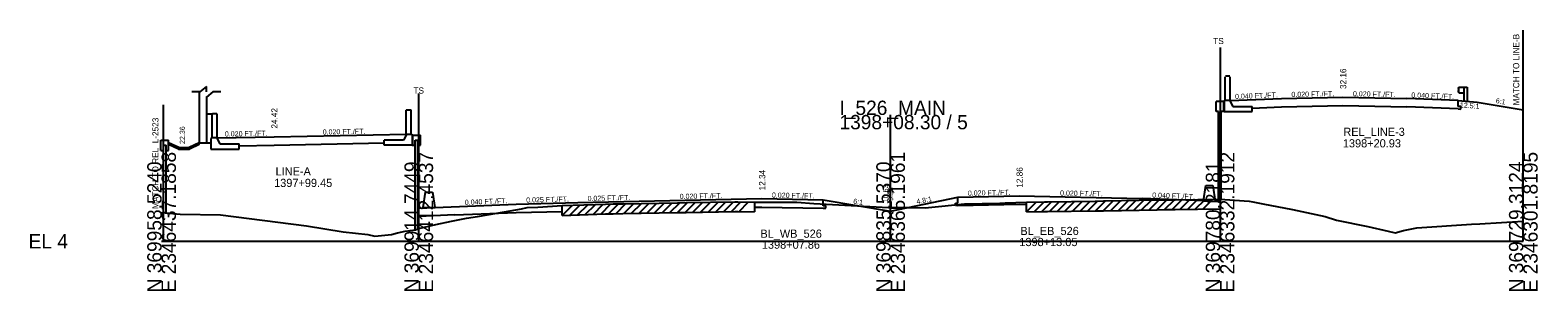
# Model space of a CAD drawing. Extents: x -170 to 2527928, y -10 to 1619750.
# Drawn here: x 1974.3 to 2269.1, y 8490.3 to 8541.3 of the extents above; entities that cross this region are included whole.
import ezdxf

# ---------------------------------------------------------------- set-up
doc = ezdxf.new("R2010")
doc.units = 0
for name, color, linetype in [('Default', 7, 'Continuous'), ('RD_GPK_XS_Cell', 7, 'Continuous'), ('RD_PD_NOISE-WALL-GM', 7, 'Continuous'), ('RD_PD_WallFill', 7, 'Continuous'), ('RD_XS_Base', 7, 'Continuous'), ('RD_XS_EarthShd', 7, 'Continuous'), ('RD_XS_ExGround', 7, 'Continuous'), ('RD_XS_ExPaveRet', 7, 'Continuous'), ('RD_XS_GR', 7, 'Continuous'), ('RD_XS_MatchLine', 7, 'Continuous'), ('RD_XS_Pave', 7, 'Continuous'), ('RD_XS_PaveShd', 7, 'Continuous'), ('RD_XS_TieSlope', 7, 'Continuous'), ('RD_XS_TX_Elev_EX', 7, 'Continuous'), ('RD_XS_TX_Elev_PR', 7, 'Continuous'), ('RD_XS_TX_Slope', 7, 'Continuous'), ('RD_XS_TX_Station', 7, 'Continuous')]:
    doc.layers.add(name, color=color, linetype=linetype)

msp = doc.modelspace()

# ---------------------------------------------------------------- linework, layer by layer
at = {"layer": 'Default'}
for p, q in [((2008.75, 8530.26), (2007.5, 8529.23)), ((2008.75, 8529.23), (2008.75, 8530.26)), ((2007.5, 8529.23), (2005.92, 8529.23)), ((2010, 8529.23), (2008.75, 8528.21)), ((2011.6, 8529.23), (2010, 8529.23))]:
    msp.add_line(p, q, dxfattribs=at)
at = {"layer": 'RD_GPK_XS_Cell'}
for p, q in [((2142.52, 8500), (2142.52, 8524.7)), ((2000, 8500), (2050.28, 8500)), ((2050.28, 8500), (2142.52, 8500)), ((2142.52, 8500), (2206.93, 8500)), ((2206.93, 8500), (2266.21, 8500))]:
    msp.add_line(p, q, dxfattribs=at)
at = {"layer": 'RD_PD_NOISE-WALL-GM'}
for p, q in [((2007.37, 8529.23), (2007.37, 8519.28)), ((2008.87, 8519.28), (2008.87, 8528.31)), ((2051.12, 8506.62), (2051.6, 8509.62)), ((2051.6, 8509.62), (2052.94, 8509.62)), ((2052.94, 8509.62), (2053.43, 8506.62)), ((2203.68, 8507.9), (2204.16, 8510.9)), ((2204.16, 8510.9), (2205.5, 8510.9)), ((2205.5, 8510.9), (2206, 8507.81)), ((2051.12, 8506.62), (2053.43, 8506.62))]:
    msp.add_line(p, q, dxfattribs=at)
at = {"layer": 'RD_PD_WallFill'}
for p, q in [((2207.93, 8527.52), (2207.93, 8532.19)), ((2208.85, 8532.27), (2208.02, 8532.27)), ((2208.93, 8527.52), (2208.93, 8532.19)), ((2206.15, 8525.35), (2206.15, 8527.35)), ((2207.65, 8527.35), (2206.15, 8527.35)), ((2207.65, 8525.35), (2207.65, 8527.35)), ((2207.72, 8527.35), (2207.65, 8527.35)), ((2207.8, 8527.52), (2207.72, 8527.43)), ((2207.72, 8527.43), (2207.72, 8525.35)), ((2208.93, 8527.52), (2207.8, 8527.52)), ((2208.93, 8527.52), (2208.93, 8527.35)), ((2208.93, 8527.35), (2209.43, 8526.35)), ((2009.96, 8524.95), (2009.87, 8524.87)), ((2009.87, 8520.2), (2009.87, 8524.87)), ((2010.79, 8524.95), (2009.96, 8524.95)), ((2010.79, 8524.95), (2010.87, 8524.87)), ((2010.87, 8520.2), (2010.87, 8524.87)), ((2047.89, 8525.69), (2047.8, 8525.61)), ((2047.8, 8520.94), (2047.8, 8525.61)), ((2047.89, 8525.69), (2048.72, 8525.69)), ((2048.72, 8525.69), (2048.8, 8525.61)), ((2048.8, 8520.94), (2048.8, 8525.61)), ((2206.65, 8525.35), (2206.15, 8525.35)), ((2206.65, 8507.78), (2206.65, 8525.35)), ((2207.15, 8508.22), (2207.15, 8525.35)), ((2207.65, 8525.35), (2207.15, 8525.35)), ((2207.72, 8525.35), (2207.65, 8525.35)), ((2207.72, 8525.35), (2213.22, 8525.35)), ((2209.43, 8526.35), (2213.22, 8526.35)), ((2213.22, 8525.35), (2213.22, 8526.35)), ((1999.87, 8519.78), (2001.37, 8519.78)), ((1999.87, 8517.78), (1999.87, 8519.78)), ((2000.37, 8505.59), (2000.37, 8518.78)), ((2000.37, 8518.78), (2000.87, 8518.78)), ((2000.87, 8505.54), (2000.87, 8518.78)), ((2001.37, 8517.78), (2001.37, 8519.78)), ((2003.37, 8518.36), (2001.37, 8519.28)), ((2003.3, 8518.03), (2001.37, 8518.91)), ((2003.37, 8518.36), (2005.37, 8518.36)), ((2007.37, 8519.28), (2005.37, 8518.36)), ((2007.37, 8518.91), (2005.45, 8518.03)), ((2007.37, 8518.91), (2007.37, 8519.28)), ((2009.75, 8520.2), (2009.66, 8520.12)), ((2009.66, 8520.12), (2009.66, 8518.03)), ((2010.87, 8520.2), (2009.75, 8520.2)), ((2010.87, 8520.2), (2010.87, 8520.03)), ((2010.87, 8520.03), (2011.37, 8519.03)), ((2011.37, 8519.03), (2015.16, 8519.03)), ((2015.16, 8518.03), (2015.16, 8519.03)), ((2047.31, 8519.77), (2043.52, 8519.77)), ((2043.52, 8518.77), (2043.52, 8519.77)), ((2049.02, 8518.77), (2043.52, 8518.77)), ((2047.8, 8520.77), (2047.31, 8519.77)), ((2047.8, 8520.94), (2048.93, 8520.94)), ((2047.8, 8520.94), (2047.8, 8520.77)), ((2048.93, 8520.94), (2049.02, 8520.86)), ((2049.02, 8520.86), (2049.02, 8518.77)), ((2049.02, 8520.77), (2049.09, 8520.77)), ((2049.02, 8518.77), (2049.09, 8518.77)), ((2049.09, 8518.77), (2049.09, 8520.77)), ((2049.09, 8520.77), (2050.59, 8520.77)), ((2049.09, 8518.77), (2049.59, 8518.77)), ((2049.59, 8519.77), (2050.09, 8519.77)), ((2049.59, 8502.25), (2049.59, 8519.77)), ((2050.09, 8502.44), (2050.09, 8519.77)), ((2050.09, 8518.77), (2050.59, 8518.77)), ((2050.59, 8518.77), (2050.59, 8520.77)), ((1999.87, 8517.78), (2000.37, 8517.78)), ((2000.87, 8517.78), (2001.37, 8517.78)), ((2003.3, 8518.03), (2005.45, 8518.03)), ((2009.66, 8518.03), (2015.16, 8518.03))]:
    msp.add_line(p, q, dxfattribs=at)
at = {"layer": 'RD_XS_Base'}
for p, q in [((2253.47, 8526.37), (2253.47, 8527.51)), ((2213.22, 8526.05), (2218.93, 8526.28)), ((2218.93, 8526.28), (2230.93, 8526.52)), ((2230.93, 8526.52), (2243.47, 8526.27)), ((2253.47, 8525.87), (2243.47, 8526.27)), ((2253.97, 8526.35), (2253.47, 8526.37)), ((2253.47, 8525.87), (2253.97, 8525.85)), ((2253.97, 8525.85), (2253.97, 8526.35)), ((2015.16, 8518.65), (2022, 8518.79)), ((2022, 8518.79), (2043.52, 8519.22)), ((2050.28, 8504.86), (2050.28, 8506.5)), ((2115.92, 8506.67), (2117.35, 8506.7)), ((2117.35, 8506.7), (2129.35, 8506.46)), ((2129.35, 8506.96), (2129.35, 8508.1)), ((2129.85, 8506.95), (2129.35, 8506.96)), ((2129.35, 8506.46), (2129.85, 8506.45)), ((2129.85, 8506.45), (2129.85, 8506.95)), ((2155.18, 8507.48), (2155.68, 8507.49)), ((2155.18, 8506.98), (2155.18, 8507.48)), ((2155.68, 8506.99), (2155.18, 8506.98)), ((2155.68, 8507.49), (2155.68, 8508.62)), ((2155.68, 8506.99), (2167.68, 8507.23)), ((2167.68, 8507.23), (2169.06, 8507.2)), ((2057.35, 8505.14), (2050.28, 8504.86)), ((2057.35, 8505.14), (2069.35, 8505.62)), ((2069.35, 8505.62), (2078.34, 8505.85))]:
    msp.add_line(p, q, dxfattribs=at)
at = {"layer": 'RD_XS_EarthShd'}
for p, q in [((2253.47, 8527.51), (2257.22, 8527.21)), ((2008.87, 8524.95), (2009.96, 8524.95)), ((2007.37, 8519.28), (2009.66, 8519.28)), ((2203.68, 8507.9), (2206.65, 8507.78))]:
    msp.add_line(p, q, dxfattribs=at)
at = {"layer": 'RD_XS_ExGround'}
msp.add_lwpolyline([(2000, 8505.62), (2003.66, 8505.29), (2011.49, 8505.18), (2028.33, 8503.03), (2035.52, 8501.87), (2040.34, 8501.3), (2041.71, 8500.97), (2044.94, 8501.33), (2046.1, 8501.67), (2047.64, 8501.97), (2048.57, 8502.13), (2049.63, 8502.27), (2050.31, 8502.49), (2053.59, 8503.27), (2056.69, 8503.94), (2059.64, 8504.5), (2061.74, 8504.87), (2065.54, 8505.49), (2069.26, 8506.12), (2070.36, 8506.35), (2071.48, 8506.58), (2073.58, 8506.68), (2078.34, 8506.98), (2086.78, 8507.28), (2088.26, 8507.32), (2090.15, 8507.35), (2100.87, 8507.54), (2102.56, 8507.57), (2112.06, 8507.72), (2112.64, 8507.71), (2115.92, 8507.67), (2122.04, 8507.65), (2124.22, 8507.65), (2127.51, 8507.36), (2142.12, 8506.63), (2142.52, 8506.63), (2143.68, 8506.63), (2145.81, 8506.6), (2149.3, 8506.57), (2152.55, 8506.88), (2156.94, 8507.3), (2163.85, 8507.48), (2164.91, 8507.51), (2169.06, 8507.66), (2172.58, 8507.73), (2173.22, 8507.74), (2182.5, 8507.87), (2184.17, 8507.9), (2194.66, 8508.09), (2196.55, 8508.12), (2198.14, 8508.13), (2206.93, 8508.23), (2211.61, 8507.9), (2212.63, 8507.83), (2213.32, 8507.7), (2215.29, 8507.32), (2221.09, 8506.22), (2227.45, 8504.82), (2229.68, 8504.11), (2235.79, 8502.86), (2239.8, 8501.95), (2241.14, 8501.68), (2242.76, 8502.11), (2245.42, 8502.64), (2256.06, 8503.34), (2257.74, 8503.44), (2266.21, 8503.96)], dxfattribs=at)
at = {"layer": 'RD_XS_ExPaveRet'}
for p, q in [((2078.34, 8505.06), (2080.33, 8507.05)), ((2078.34, 8505.06), (2078.34, 8506.98)), ((2079.84, 8505.11), (2081.83, 8507.1)), ((2081.34, 8505.17), (2083.33, 8507.16)), ((2082.84, 8505.22), (2084.83, 8507.21)), ((2084.34, 8505.27), (2086.33, 8507.26)), ((2085.84, 8505.33), (2087.82, 8507.31)), ((2087.34, 8505.38), (2089.3, 8507.34)), ((2088.84, 8505.41), (2090.79, 8507.37)), ((2090.34, 8505.44), (2092.29, 8507.39)), ((2091.84, 8505.47), (2093.79, 8507.42)), ((2093.34, 8505.49), (2095.29, 8507.44)), ((2094.84, 8505.52), (2096.79, 8507.47)), ((2096.34, 8505.55), (2098.29, 8507.5)), ((2097.84, 8505.57), (2099.79, 8507.52)), ((2099.34, 8505.6), (2101.29, 8507.55)), ((2100.84, 8505.62), (2102.79, 8507.57)), ((2102.34, 8505.65), (2104.29, 8507.59)), ((2103.84, 8505.67), (2105.79, 8507.62)), ((2105.34, 8505.69), (2107.29, 8507.64)), ((2106.84, 8505.72), (2108.79, 8507.67)), ((2108.34, 8505.74), (2110.29, 8507.69)), ((2109.84, 8505.77), (2111.79, 8507.71)), ((2111.34, 8505.79), (2113.26, 8507.7)), ((2112.84, 8505.79), (2114.73, 8507.69)), ((2115.92, 8507.67), (2115.92, 8505.75)), ((2169.06, 8505.74), (2171.02, 8507.69)), ((2169.06, 8505.74), (2169.06, 8507.66)), ((2170.56, 8505.77), (2172.52, 8507.72)), ((2172.06, 8505.8), (2174.02, 8507.75)), ((2173.56, 8505.83), (2175.51, 8507.77)), ((2175.06, 8505.85), (2177.01, 8507.79)), ((2176.56, 8505.87), (2178.51, 8507.82)), ((2178.06, 8505.89), (2180.01, 8507.84)), ((2179.56, 8505.91), (2181.51, 8507.86)), ((2181.06, 8505.94), (2183.01, 8507.88)), ((2182.56, 8505.96), (2184.51, 8507.9)), ((2184.06, 8505.98), (2186.02, 8507.93)), ((2185.56, 8506.01), (2187.52, 8507.96)), ((2187.06, 8506.03), (2189.02, 8507.99)), ((2188.56, 8506.06), (2190.52, 8508.01)), ((2190.06, 8506.09), (2192.02, 8508.04)), ((2191.56, 8506.12), (2193.52, 8508.07)), ((2193.06, 8506.14), (2195.02, 8508.1)), ((2194.56, 8506.17), (2196.51, 8508.12)), ((2196.06, 8506.2), (2198, 8508.13)), ((2197.56, 8506.21), (2199.5, 8508.15)), ((2198.14, 8506.22), (2206.93, 8506.32)), ((2199.06, 8506.23), (2201, 8508.17)), ((2200.56, 8506.24), (2202.5, 8508.18)), ((2202.06, 8506.26), (2204, 8508.2)), ((2203.56, 8506.28), (2205.5, 8508.22)), ((2206.93, 8508.23), (2206.93, 8506.32)), ((2078.34, 8505.06), (2086.78, 8505.36)), ((2086.78, 8505.36), (2088.26, 8505.4)), ((2088.26, 8505.4), (2090.15, 8505.44)), ((2090.15, 8505.44), (2100.87, 8505.62)), ((2100.87, 8505.62), (2102.56, 8505.65)), ((2102.56, 8505.65), (2112.06, 8505.8)), ((2112.06, 8505.8), (2112.64, 8505.8)), ((2112.64, 8505.8), (2115.92, 8505.75)), ((2169.06, 8505.74), (2172.58, 8505.81)), ((2172.58, 8505.81), (2173.22, 8505.82)), ((2173.22, 8505.82), (2182.5, 8505.96)), ((2182.5, 8505.96), (2184.17, 8505.98)), ((2184.17, 8505.98), (2194.66, 8506.17)), ((2194.66, 8506.17), (2196.55, 8506.21)), ((2196.55, 8506.21), (2198.14, 8506.22))]:
    msp.add_line(p, q, dxfattribs=at)
at = {"layer": 'RD_XS_GR'}
for p, q in [((2253.63, 8530.09), (2253.47, 8529.89)), ((2253.47, 8529.89), (2253.47, 8529.84)), ((2253.63, 8529), (2253.63, 8530.16)), ((2253.63, 8530.16), (2254.55, 8530.16)), ((2254.55, 8530.16), (2255.22, 8530.16)), ((2254.55, 8530.16), (2254.55, 8527.42)), ((2255.22, 8530.16), (2255.22, 8527.37)), ((2253.47, 8529.84), (2253.63, 8529.64)), ((2253.47, 8529.32), (2253.63, 8529.52)), ((2253.47, 8529.27), (2253.47, 8529.32)), ((2253.63, 8529.07), (2253.47, 8529.27)), ((2253.63, 8529), (2254.55, 8529))]:
    msp.add_line(p, q, dxfattribs=at)
at = {"layer": 'RD_XS_MatchLine'}
for p, q in [((2266.21, 8500), (2266.21, 8541.29)), ((2206.93, 8537.89), (2206.93, 8500)), ((2050.28, 8500), (2050.28, 8528.88)), ((2000.37, 8500), (2000.37, 8526.65))]:
    msp.add_line(p, q, dxfattribs=at)
at = {"layer": 'RD_XS_Pave'}
for p, q in [((2218.93, 8527.92), (2230.93, 8528.16)), ((2230.93, 8528.16), (2243.47, 8527.91)), ((2022, 8520.42), (2047.8, 8520.94)), ((2069.35, 8507.26), (2081.35, 8507.56)), ((2081.35, 8507.56), (2093.35, 8507.86)), ((2093.35, 8507.86), (2117.35, 8508.34)), ((2167.68, 8508.86), (2191.68, 8508.38))]:
    msp.add_line(p, q, dxfattribs=at)
at = {"layer": 'RD_XS_PaveShd'}
for p, q in [((2208.93, 8527.52), (2218.93, 8527.92)), ((2253.47, 8527.51), (2243.47, 8527.91)), ((2010.87, 8520.2), (2022, 8520.42)), ((2050.28, 8506.5), (2069.35, 8507.26)), ((2117.35, 8508.34), (2129.35, 8508.1)), ((2155.68, 8508.62), (2167.68, 8508.86)), ((2203.68, 8507.9), (2191.68, 8508.38))]:
    msp.add_line(p, q, dxfattribs=at)
at = {"layer": 'RD_XS_TieSlope'}
for p, q in [((2257.22, 8527.21), (2266.21, 8525.71)), ((2129.35, 8508.1), (2142.52, 8505.9)), ((2142.52, 8505.9), (2155.68, 8508.62))]:
    msp.add_line(p, q, dxfattribs=at)

# ---------------------------------------------------------------- texts
at = {"layer": 'RD_GPK_XS_Cell'}
for s, p in [('I_526_MAIN', (2132.52, 8524.7)), ('1398+08.30 / 5', (2132.52, 8521.9)), ('EL 4', (1974, 8498.6))]:
    msp.add_text(s, height=2.8, dxfattribs=at).set_placement(p)
for s, p in [('N 369958.5240', (2000, 8490)), ('E 2346437.1858', (2002.8, 8490)), ('N 369914.7449', (2050.28, 8490)), ('E 2346412.4537', (2053.08, 8490)), ('N 369835.5370', (2142.52, 8490)), ('E 2346365.1961', (2145.32, 8490)), ('N 369780.2181', (2206.93, 8490)), ('E 2346332.1912', (2209.73, 8490)), ('N 369729.3124', (2266.21, 8490)), ('E 2346301.8195', (2269.01, 8490))]:
    msp.add_text(s, height=2.8, rotation=90, dxfattribs=at).set_placement(p)
at = {"layer": 'RD_XS_MatchLine'}
for p in [(2205.6, 8538.56), (2049.25, 8528.88)]:
    msp.add_text('TS', height=1.2, dxfattribs=at).set_placement(p)
for s, p in [('MATCH TO LINE-B', (2265.41, 8526.56)), ('MATCH TO REL_L-2523', (1999.39, 8506.33))]:
    msp.add_text(s, height=1.2, rotation=90, dxfattribs=at).set_placement(p)
at = {"layer": 'RD_XS_TX_Elev_EX'}
msp.add_text('10.63', height=1, rotation=90, dxfattribs=at).set_placement((2142.02, 8507.63))
at = {"layer": 'RD_XS_TX_Elev_PR'}
msp.add_text('9.90', height=1, rotation=90, dxfattribs=at).set_placement((2143.02, 8507.9))
at = {"layer": 'RD_XS_TX_Slope'}
for s, rotation, p in [('0.040 FT./FT.', 2.2906, (2209.87, 8527.81)), ('0.020 FT./FT.', 1.1458, (2220.88, 8528.21)), ('0.020 FT./FT.', 358.8542, (2232.89, 8528.37)), ('0.040 FT./FT.', 357.7094, (2244.3, 8528.12)), ('12.5:1', 355.4261, (2253.77, 8526.18)), ('6:1', 350.5377, (2260.76, 8527.04)), ('22.36', 90, (2004.55, 8519.03)), ('0.020 FT./FT.', 1.1458, (2012.38, 8520.48)), ('0.020 FT./FT.', 1.1458, (2031.5, 8520.86)), ('0.020 FT./FT.', 1.1458, (2101.29, 8508.27)), ('0.020 FT./FT.', 358.8542, (2119.3, 8508.55)), ('0.020 FT./FT.', 1.1458, (2157.63, 8508.91)), ('0.020 FT./FT.', 358.8542, (2175.64, 8508.95)), ('0.040 FT./FT.', 357.7094, (2193.64, 8508.55)), ('0.040 FT./FT.', 2.2906, (2059.29, 8507.11)), ('0.025 FT./FT.', 1.4321, (2071.29, 8507.56)), ('0.025 FT./FT.', 1.4321, (2083.29, 8507.86)), ('6:1', 350.5377, (2135.15, 8507.39)), ('4.8:1', 11.6639, (2147.67, 8507.22))]:
    msp.add_text(s, height=1, rotation=rotation, dxfattribs=at).set_placement(p)
at = {"layer": 'RD_XS_TX_Station'}
for s, p in [(' 32.16', (2231.59, 8529.33)), (' 24.42', (2022.66, 8521.59)), (' 12.34', (2118.01, 8509.51)), (' 12.86', (2168.34, 8510.03))]:
    msp.add_text(s, height=1.2, rotation=90, dxfattribs=at).set_placement(p)
for s, p in [('REL_LINE-3', (2231.03, 8520.61)), ('1398+20.93', (2230.93, 8518.36)), ('1397+99.45', (2022, 8510.62)), ('LINE-A', (2022.29, 8512.88)), ('BL_WB_526', (2117.06, 8500.69)), ('1398+13.05', (2167.68, 8499.06)), ('BL_EB_526', (2167.88, 8501.22)), ('1398+07.86', (2117.35, 8498.54))]:
    msp.add_text(s, height=1.6, dxfattribs=at).set_placement(p)

doc.saveas('drawing.dxf')
